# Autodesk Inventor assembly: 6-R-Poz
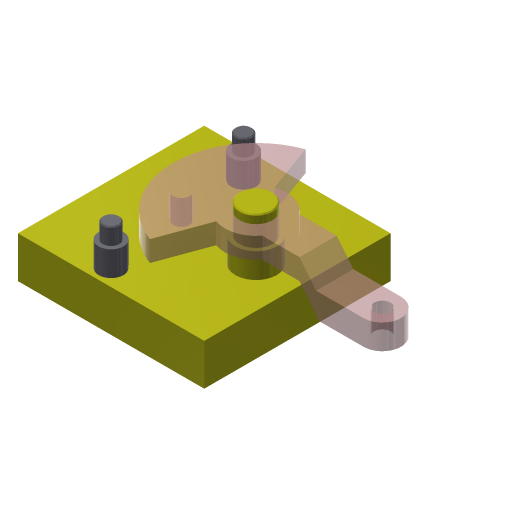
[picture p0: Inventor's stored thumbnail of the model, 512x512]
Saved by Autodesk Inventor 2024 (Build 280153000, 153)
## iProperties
Created: 2023-03
Part Number: 6-R-Poz
Document SubType Name: Zespół
Designer: Andrzej Jaskulski
Checked By: A.J.
Engr Approved By: Andrzej Jaskulski
Mfg Approved By: Andrzej Jaskulski
Authority: A.J.
Company: ATC
Control State: 0
Master: False
Checked Out: False
Shininess: 64.0
Angle Display Precision: 2
Document Length Units: 11269
Document Angle Units: 11279
Document Time Units: 11290
Document Mass Units: 11283
Document Length Units Precision: 3
Document Angle Units Precision: 2
Density: 0.0
Volumn: 0.0
Area: 0.0
PropertySet Name: Model Information
Title: A.J.: Kurs R2024-MEP
Author: Andrzej Jaskulski
Revision Number: 1/24
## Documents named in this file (4)
- C:\Users\AndJas\Documents\R2024-MEP\Obszar roboczy\6-R-Poz.iam
- C:\Users\AndJas\Documents\R2024-MEP\Obszar roboczy\Poz-Kołek.ipt
- C:\Users\AndJas\Documents\R2024-MEP\Obszar roboczy\Poz-Korpus.ipt
- C:\Users\AndJas\Documents\R2024-MEP\Obszar roboczy\Poz-Dźwignia.ipt
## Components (4 placed, 3 different names)
1. Poz-Korpus:1 — Zestawiające:1, Zestawiające:2, Napędowe
2. Poz-Kołek:1
3. Poz-Kołek:5
4. Poz-Dźwignia:1 — Zestawiające:1, Zestawiające:2, Napędowe
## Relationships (3: Mate 2, Angle 1)
- Zestawiające:1 [Mate]: Poz-Korpus:1 ↔ Poz-Dźwignia:1
- Zestawiające:2 [Mate]: Poz-Korpus:1 ↔ Poz-Dźwignia:1
- Napędowe [Angle]: Poz-Korpus:1 ↔ Poz-Dźwignia:1
